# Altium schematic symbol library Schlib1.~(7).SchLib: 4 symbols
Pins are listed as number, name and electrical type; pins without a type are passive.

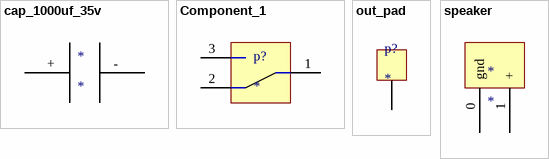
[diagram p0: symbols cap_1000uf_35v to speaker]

## cap_1000uf_35v
designator *
pins: +, -

## Component_1
designator p?
pins: 1 in, 2, 3

## out_pad
designator p?
footprint pad
pins: 0

## speaker
designator *
footprint speaker
pins: 0 gnd, 1 +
